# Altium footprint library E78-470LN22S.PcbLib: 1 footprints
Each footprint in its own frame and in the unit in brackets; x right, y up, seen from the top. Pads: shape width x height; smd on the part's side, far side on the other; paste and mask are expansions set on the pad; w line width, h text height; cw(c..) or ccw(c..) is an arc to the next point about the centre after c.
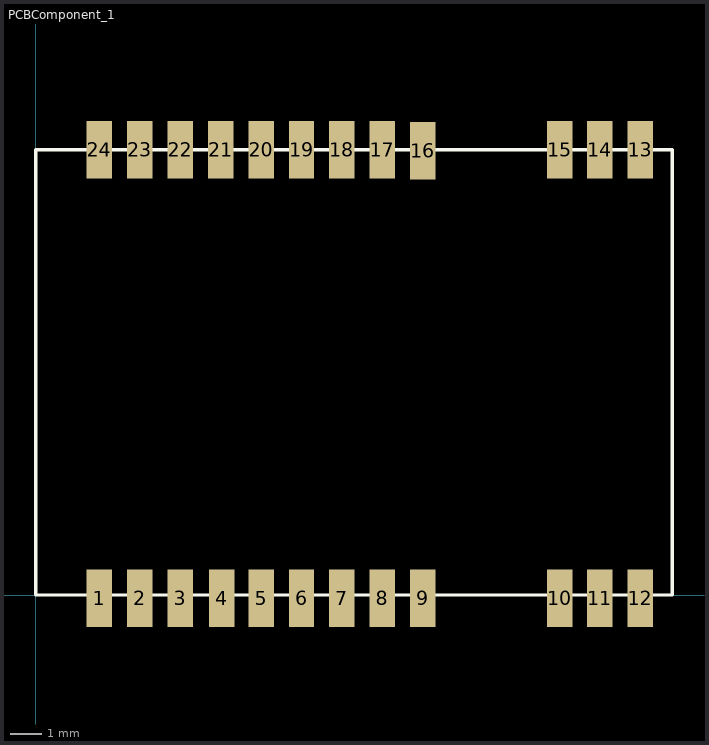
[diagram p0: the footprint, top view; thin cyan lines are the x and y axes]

## PCBComponent_1 [mm]
pads (24):
  rect 0.8x1.8 smd: 1(2,-0.1) 2(3.27,-0.1) 3(4.54,-0.1) 4(5.85,-0.1) 5(7.08,-0.1) 6(8.35,-0.1) 7(9.62,-0.1) 8(10.89,-0.1) 9(12.16,-0.1) 10(16.46,-0.1) 11(17.73,-0.1) 12(19,-0.1) 13(19,14) 14(17.73,14) 15(16.46,14) 16(12.16,13.97) 17(10.89,14) 18(9.62,14) 19(8.35,14) 20(7.08,14) 21(5.81,14) 22(4.54,14) 23(3.27,14) 24(2,14)
Top Overlay:
  lines w0.1: 0,0 0,14 20,14 20,0 0,0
